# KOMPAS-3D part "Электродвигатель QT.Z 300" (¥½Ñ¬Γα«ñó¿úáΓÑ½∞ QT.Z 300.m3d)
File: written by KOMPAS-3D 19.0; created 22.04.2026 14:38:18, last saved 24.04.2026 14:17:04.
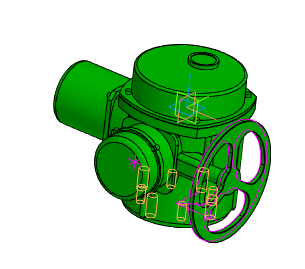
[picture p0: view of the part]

Document properties: Автор: Энергия; Полное имя файла: Z:\3.Личные\kachalov\3d для проектировщиков\1.7 Тип 023F.Z Затвор дисковый поворотный фланцевый с двумя эксцентриками\Привод\Электродвигатель QT.Z 300.m3d

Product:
- Part/product: Электродвигатель QT.Z 300
    Масса: 119.537

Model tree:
1. Эскиз:1
2. Элемент вращения:1
     Угол 1 = 360
3. Эскиз:2  (with: Элемент вращения:1)
4. Элемент выдавливания:1  (with: Элемент вращения:1)
     Расстояние 2 = 83
5. Эскиз:3  (with: Элемент вращения:1)
6. Элемент выдавливания:2
     Расстояние 1 = 197
7. Эскиз:4  (with: Элемент выдавливания:2)
8. Элемент выдавливания:3
     Расстояние 1 = 10
9. Эскиз:5  (with: Элемент выдавливания:2, Элемент выдавливания:3)
10. Элемент выдавливания:4  (with: Элемент вращения:1)
     Расстояние 1 = -197
11. Массив по концентрической сетке:1  (with: Элемент выдавливания:4, Эскиз:5, Элемент выдавливания:2)  (6 pattern instances)
     Шаг 2 = 360
12. Эскиз:6  (with: Элемент выдавливания:1)
13. Элемент выдавливания:5
     Расстояние 1 = 130
14. Эскиз:7  (with: Элемент выдавливания:5)
15. Элемент выдавливания:6
     Расстояние 1 = 10
16. Эскиз:9  (with: Элемент выдавливания:6)
17. Элемент вращения:3
     Угол 1 = 360
18. Эскиз:10  (with: Элемент выдавливания:1)
19. Элемент выдавливания:8
     Расстояние 1 = 110
20. Эскиз:11  (with: Элемент выдавливания:8)
21. Элемент выдавливания:9
     Расстояние 1 = 8
22. Эскиз:12  (with: Элемент выдавливания:9)
23. Элемент выдавливания:10
     Расстояние 1 = 39
24. Эскиз:19  (with: Элемент выдавливания:10)
25. Эскиз:20  (with: Элемент выдавливания:10)
26. Элемент выдавливания:14
     Расстояние 1 = 10
27. Эскиз:21  (with: Элемент выдавливания:14)
28. Элемент выдавливания:15
     Расстояние 1 = 40
29. Скругление:3  (with: Элемент выдавливания:15)
     Радиус = 10
30. Скругление:4  (with: Элемент выдавливания:14, Элемент выдавливания:15, Элемент выдавливания:10)
     Радиус = 2
31. Эскиз:23  (with: Элемент вращения:1)
32. Элемент выдавливания:16
     Расстояние 1 = 8
33. Эскиз:24  (with: Элемент выдавливания:16)
34. Элемент выдавливания:17
     Расстояние 2 = 2
35. Эскиз:25
36. Элемент выдавливания:19
     Расстояние 1 = 117
37. Эскиз:26  (with: Элемент выдавливания:19)
38. Элемент выдавливания:20
     Расстояние 1 = 44
39. Эскиз:27  (with: Элемент выдавливания:20)
40. Элемент выдавливания:21
     Расстояние 1 = 10
41. Эскиз:28  (with: Элемент выдавливания:21)
42. Элемент выдавливания:22
     Расстояние 1 = 10
43. Эскиз:29  (with: Элемент выдавливания:3)
44. Эскиз:30  (with: Элемент выдавливания:3)
45. Элемент выдавливания:23
     Расстояние 2 = 90
46. Эскиз:31  (with: Элемент выдавливания:3)
47. Элемент выдавливания:24
     Расстояние 2 = 2
48. Эскиз:32  (with: Элемент выдавливания:6)
49. Элемент выдавливания:25
     Расстояние 1 = 7
50. Эскиз:33  (with: Элемент вращения:1)
51. Элемент выдавливания:26
     Расстояние 1 = 7
52. Эскиз:34  (with: Элемент выдавливания:14)
53. Элемент выдавливания:27
     Расстояние 1 = 5
54. Скругление:6  (with: Элемент выдавливания:22)
     Радиус = 1
55. Эскиз:35  (with: Элемент выдавливания:2, Элемент выдавливания:4)
56. Элемент выдавливания:28
     Расстояние 1 = 5
57. Скругление:7  (with: Элемент вращения:1)
     Радиус = 5
58. Эскиз:36  (with: Элемент вращения:1)
59. Отверстие:3  (with: Элемент выдавливания:3)  (labels: M20)
     Глубина выреза = 50; Диаметр отверстия = 17.2937; Угол конуса дна = 118; Расстояние 1 = 82.5; Диаметр зенковки = 22; Глубина зенковки = 2.35316; Угол зенковки = 90
60. M20  (labels: M20; cil0_24705-2004 coarse)
     Длина резьбы = 45; Шаг резьбы = 2.5; Номинальный диаметр резьбы = 20
61. Отверстие:4  (with: Элемент выдавливания:3)  (labels: M16)
     Глубина выреза = 40; Диаметр отверстия = 13.8349; Угол конуса дна = 118; Расстояние 1 = 49.4975; Расстояние 2 = -49.4975; Диаметр зенковки = 18; Глубина зенковки = 2.08253; Угол зенковки = 90
62. M16  (labels: M16; cil0_24705-2004 coarse)
     Длина резьбы = 35; Шаг резьбы = 2; Номинальный диаметр резьбы = 16
63. Массив по концентрической сетке:4  (with: Отверстие:3, Эскиз:29)  (labels: M20)  (2 pattern instances)
64. M12  (with: Отверстие:3, Эскиз:29)  (labels: M20; cil0_24705-2004 coarse)  (1 pattern instances)
     Длина резьбы = 45; Шаг резьбы = 2.5; Номинальный диаметр резьбы = 20
65. Отверстие:3  (with: Эскиз:29)  (labels: M20)
66. Массив по концентрической сетке:5  (with: Отверстие:4, Эскиз:29)  (labels: M16)  (2 pattern instances)
67. M10  (with: Отверстие:4, Эскиз:29)  (labels: M16; cil0_24705-2004 coarse)  (1 pattern instances)
     Длина резьбы = 35; Шаг резьбы = 2; Номинальный диаметр резьбы = 16
68. Отверстие:4  (with: Эскиз:29)  (labels: M16)
69. Эскиз:38  (with: Элемент вращения:1)
70. Эскиз:39  (with: Элемент вращения:1)

Expressions: 360/4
